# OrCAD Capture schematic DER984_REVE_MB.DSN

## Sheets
1 PAGE1: size B; title: 720W, 48V  LCS_SR; rev: A
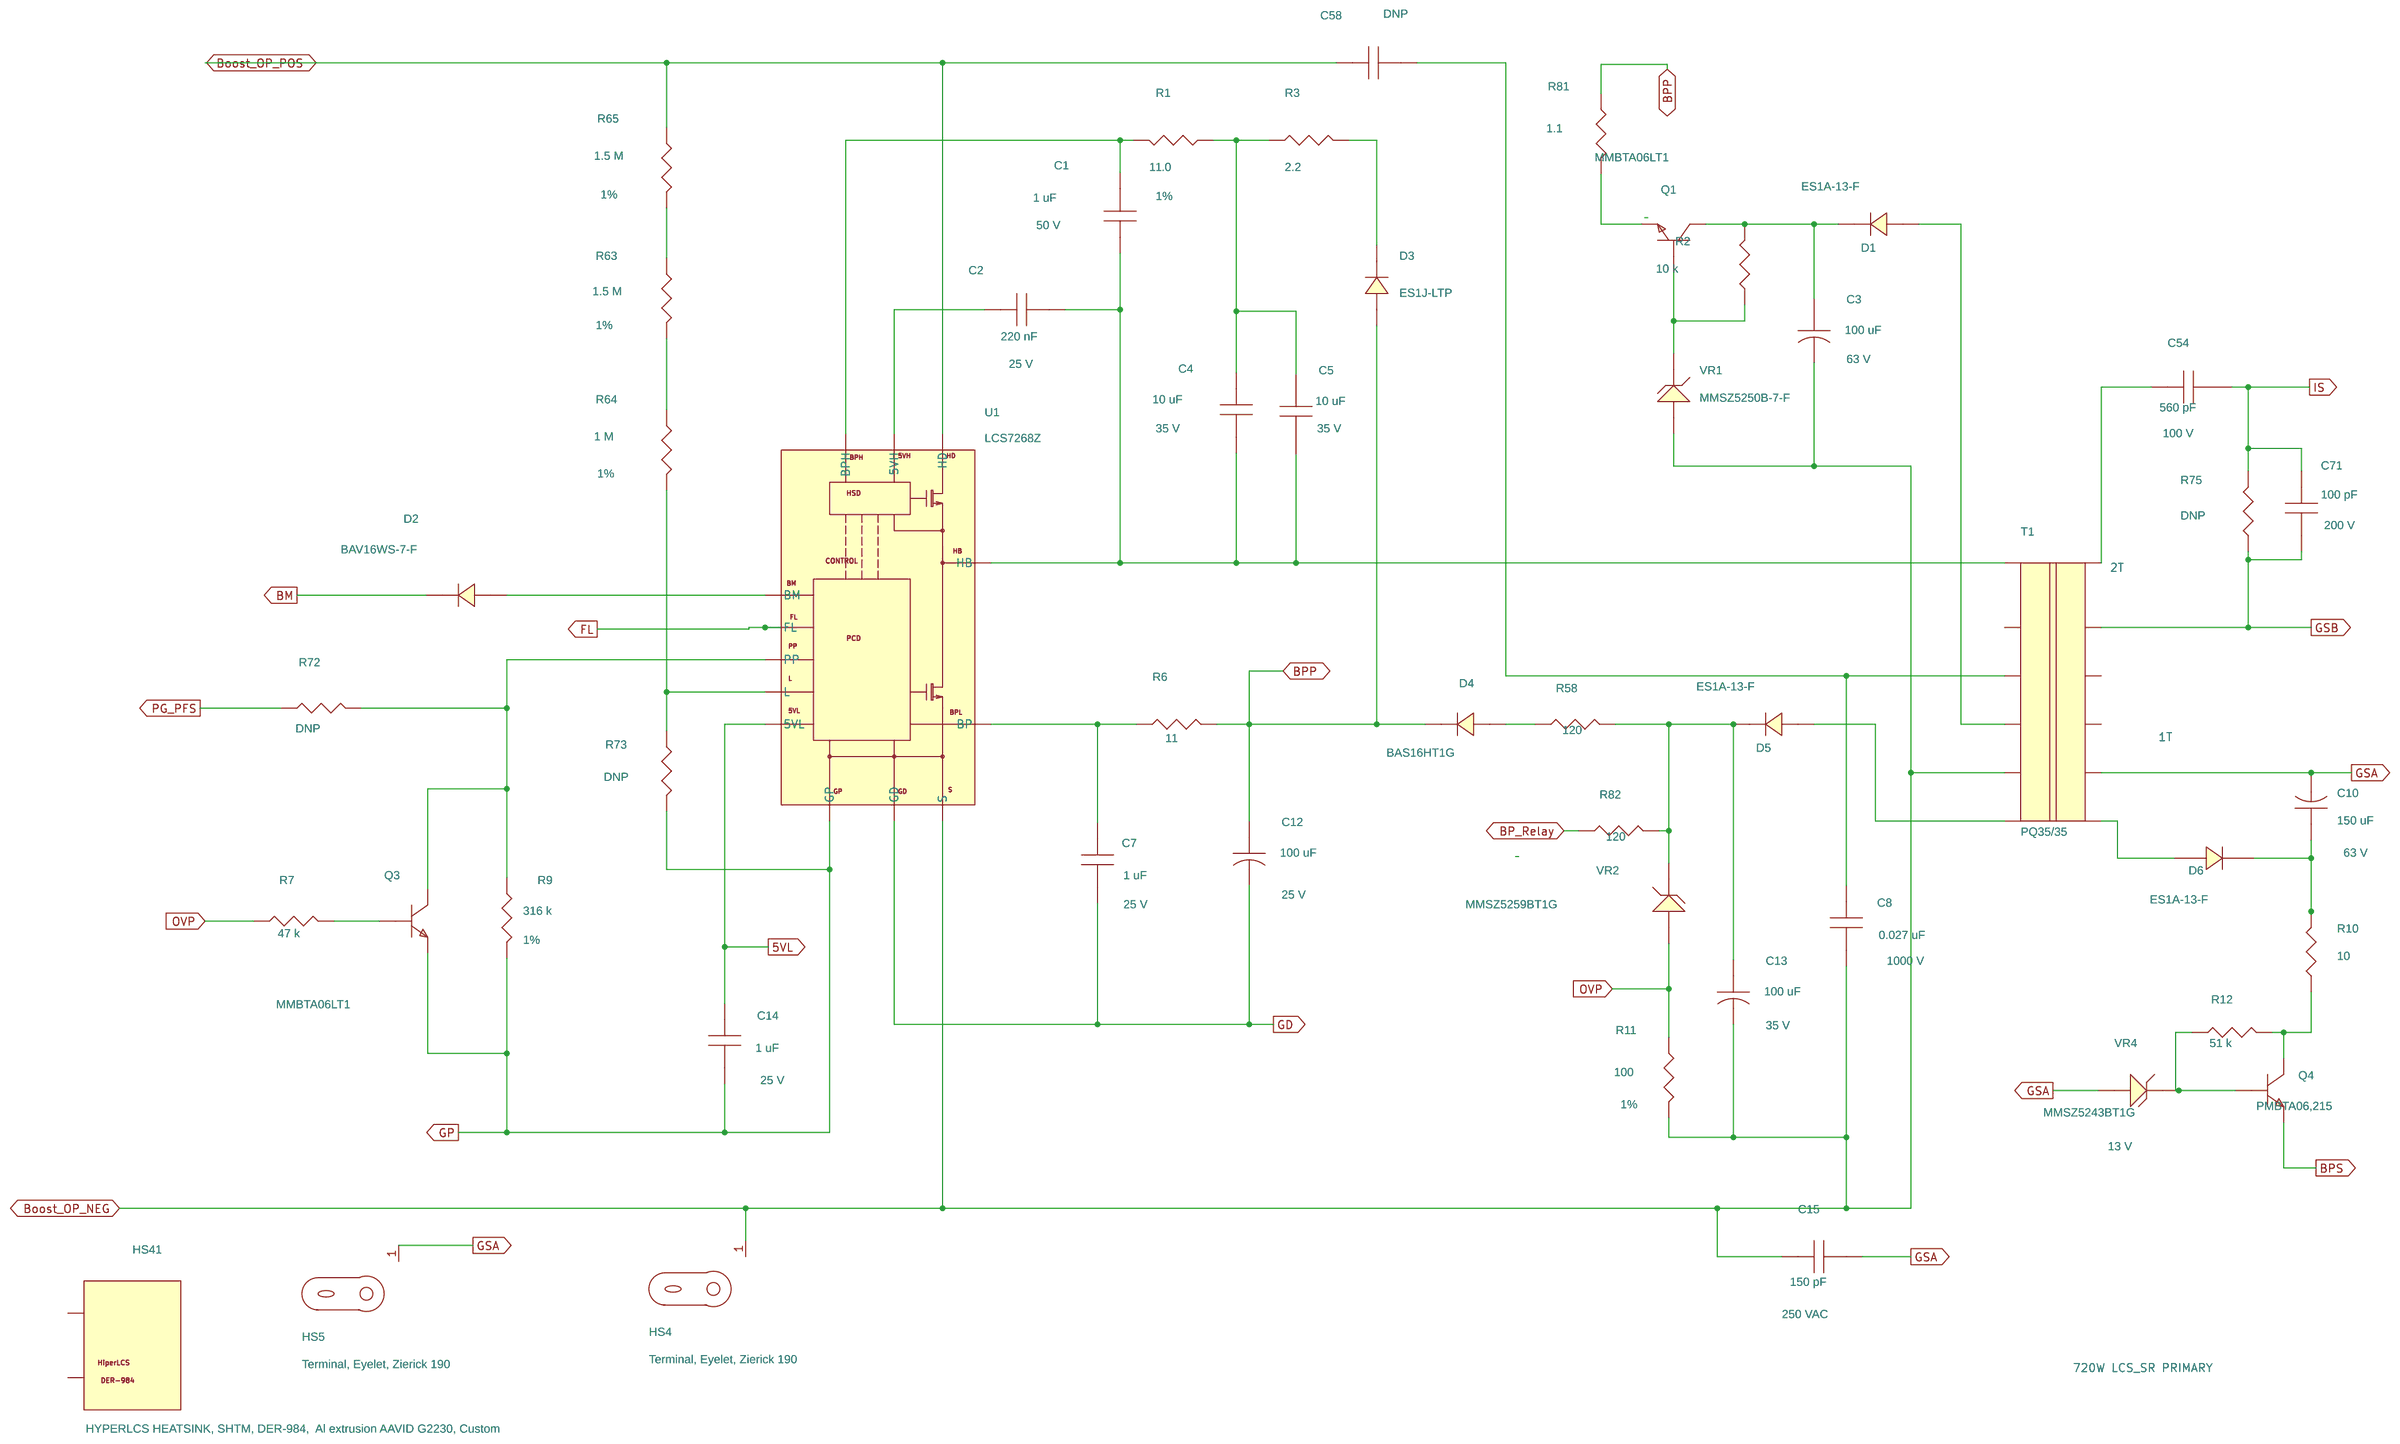
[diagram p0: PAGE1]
2 PAGE2: size B; title: 720W, 48V LCS_SR
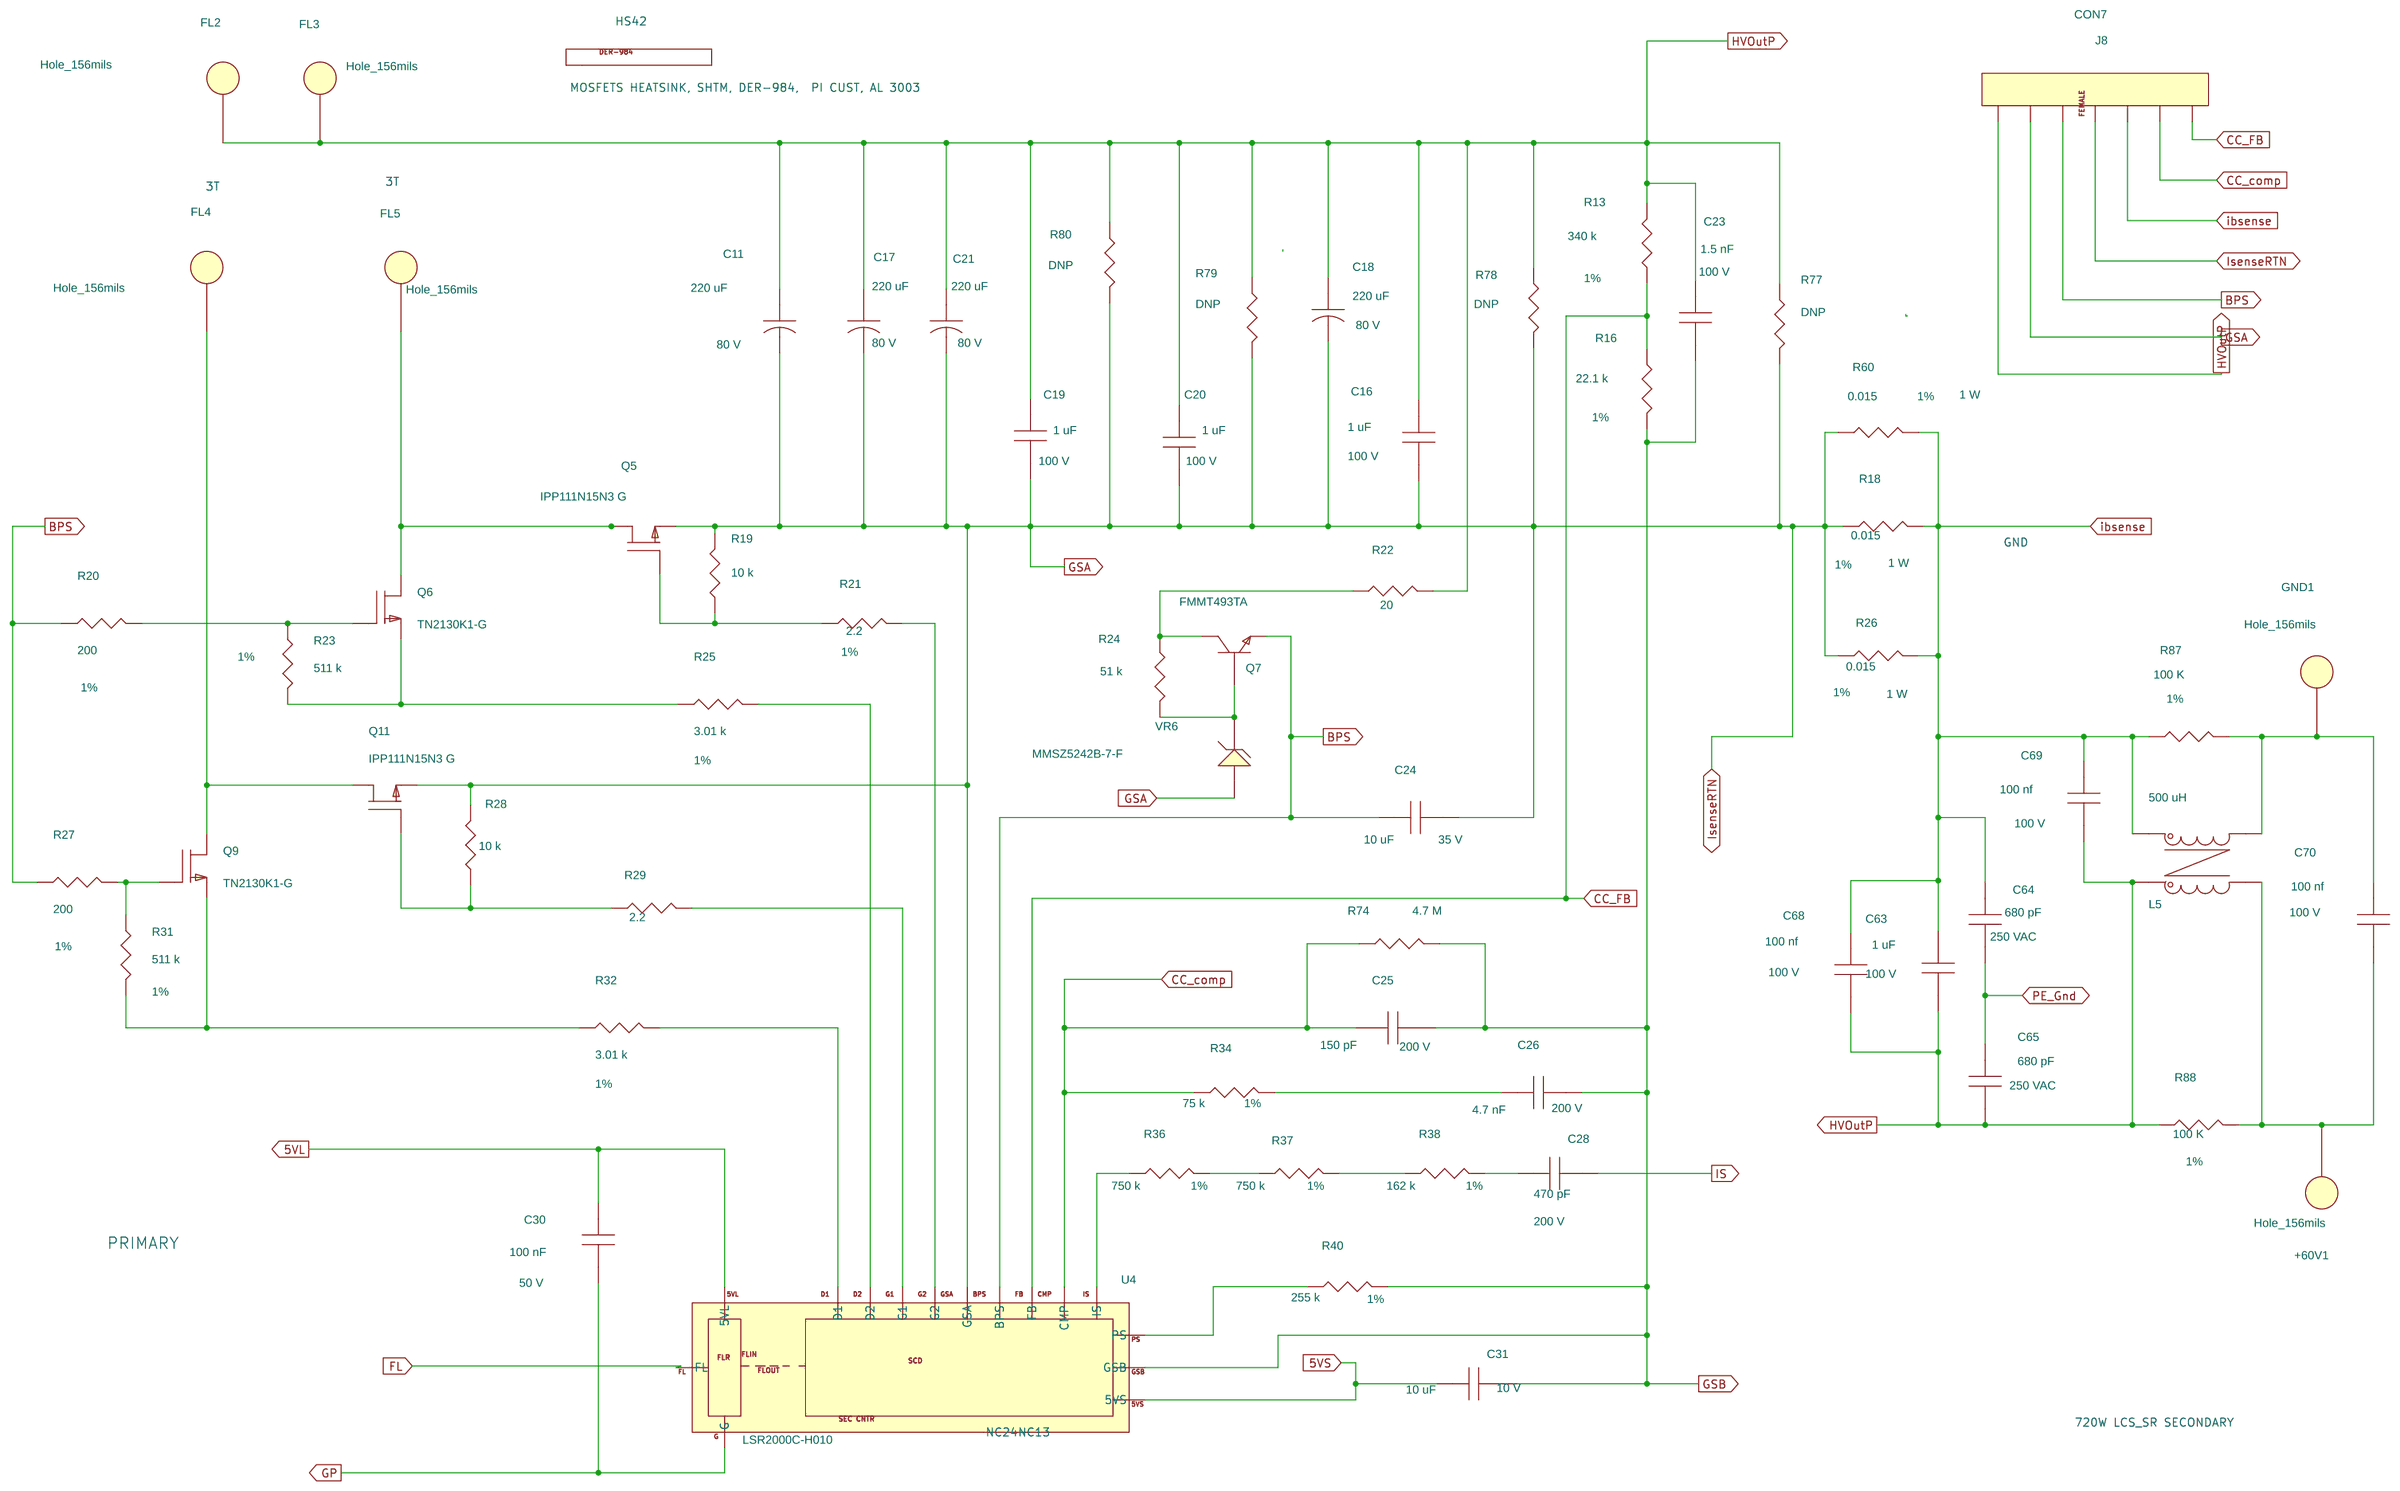
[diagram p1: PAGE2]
3 PAGE3: size C
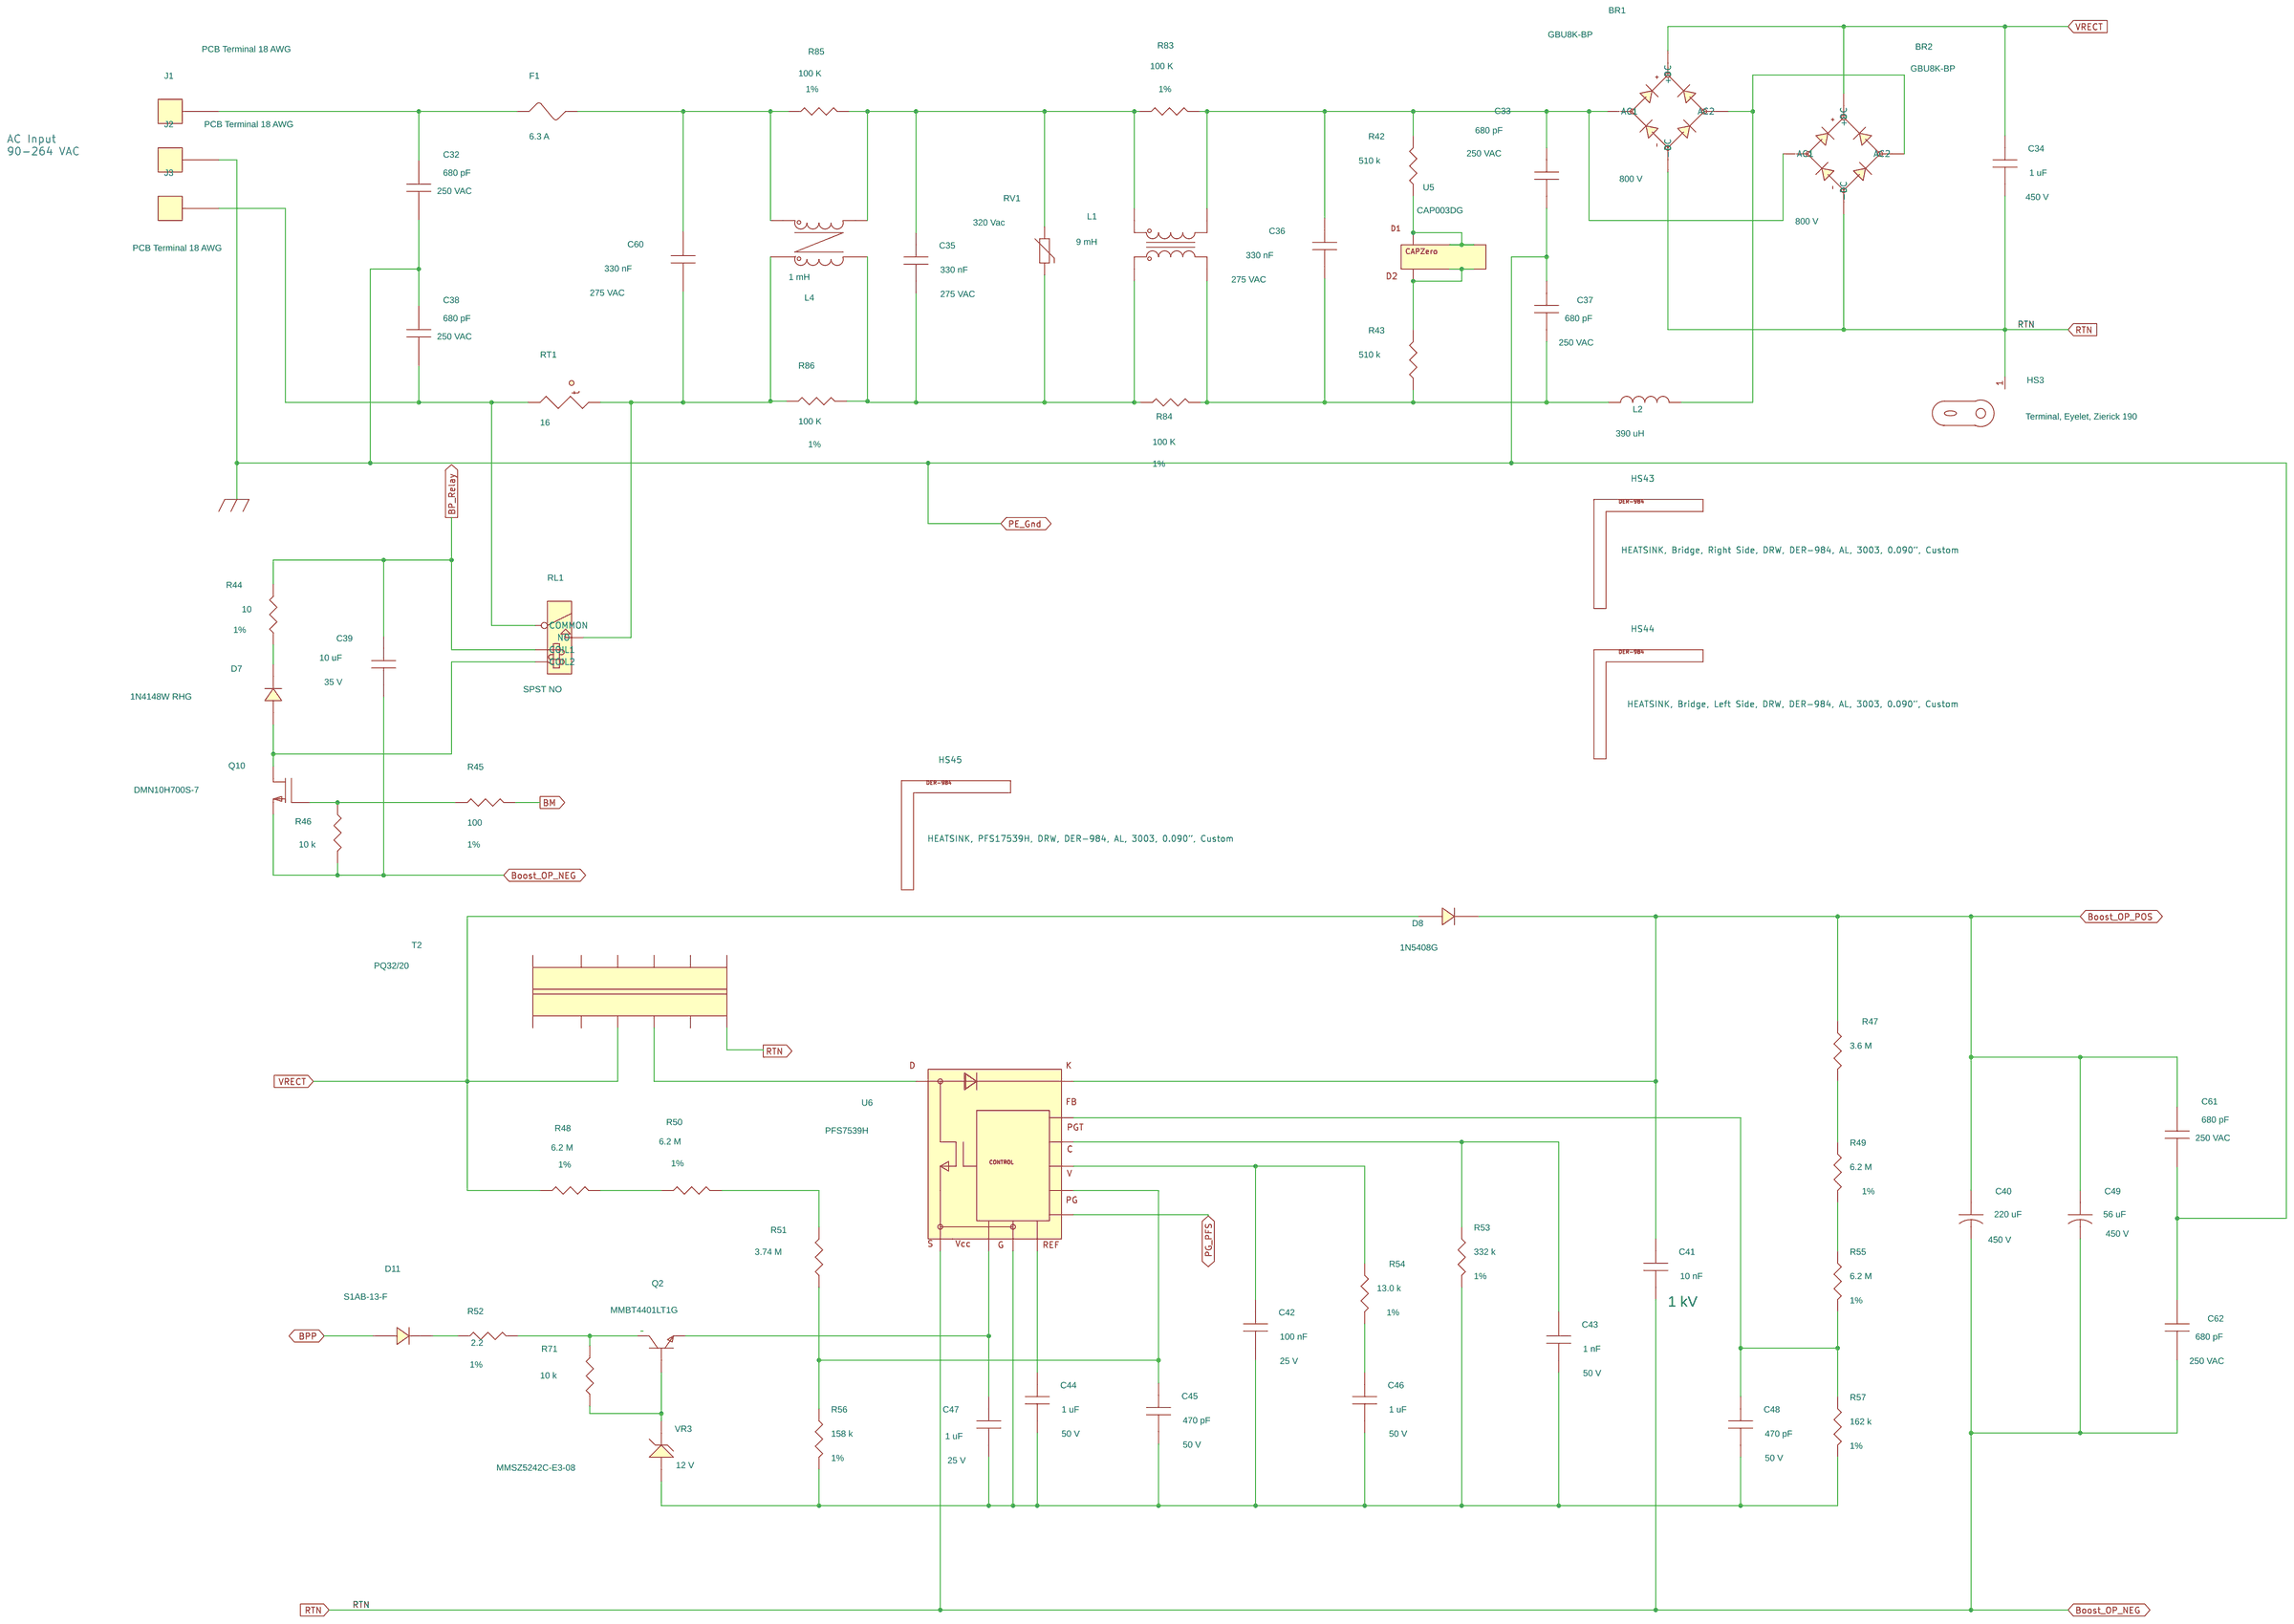
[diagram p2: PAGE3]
4 PAGE4: size C
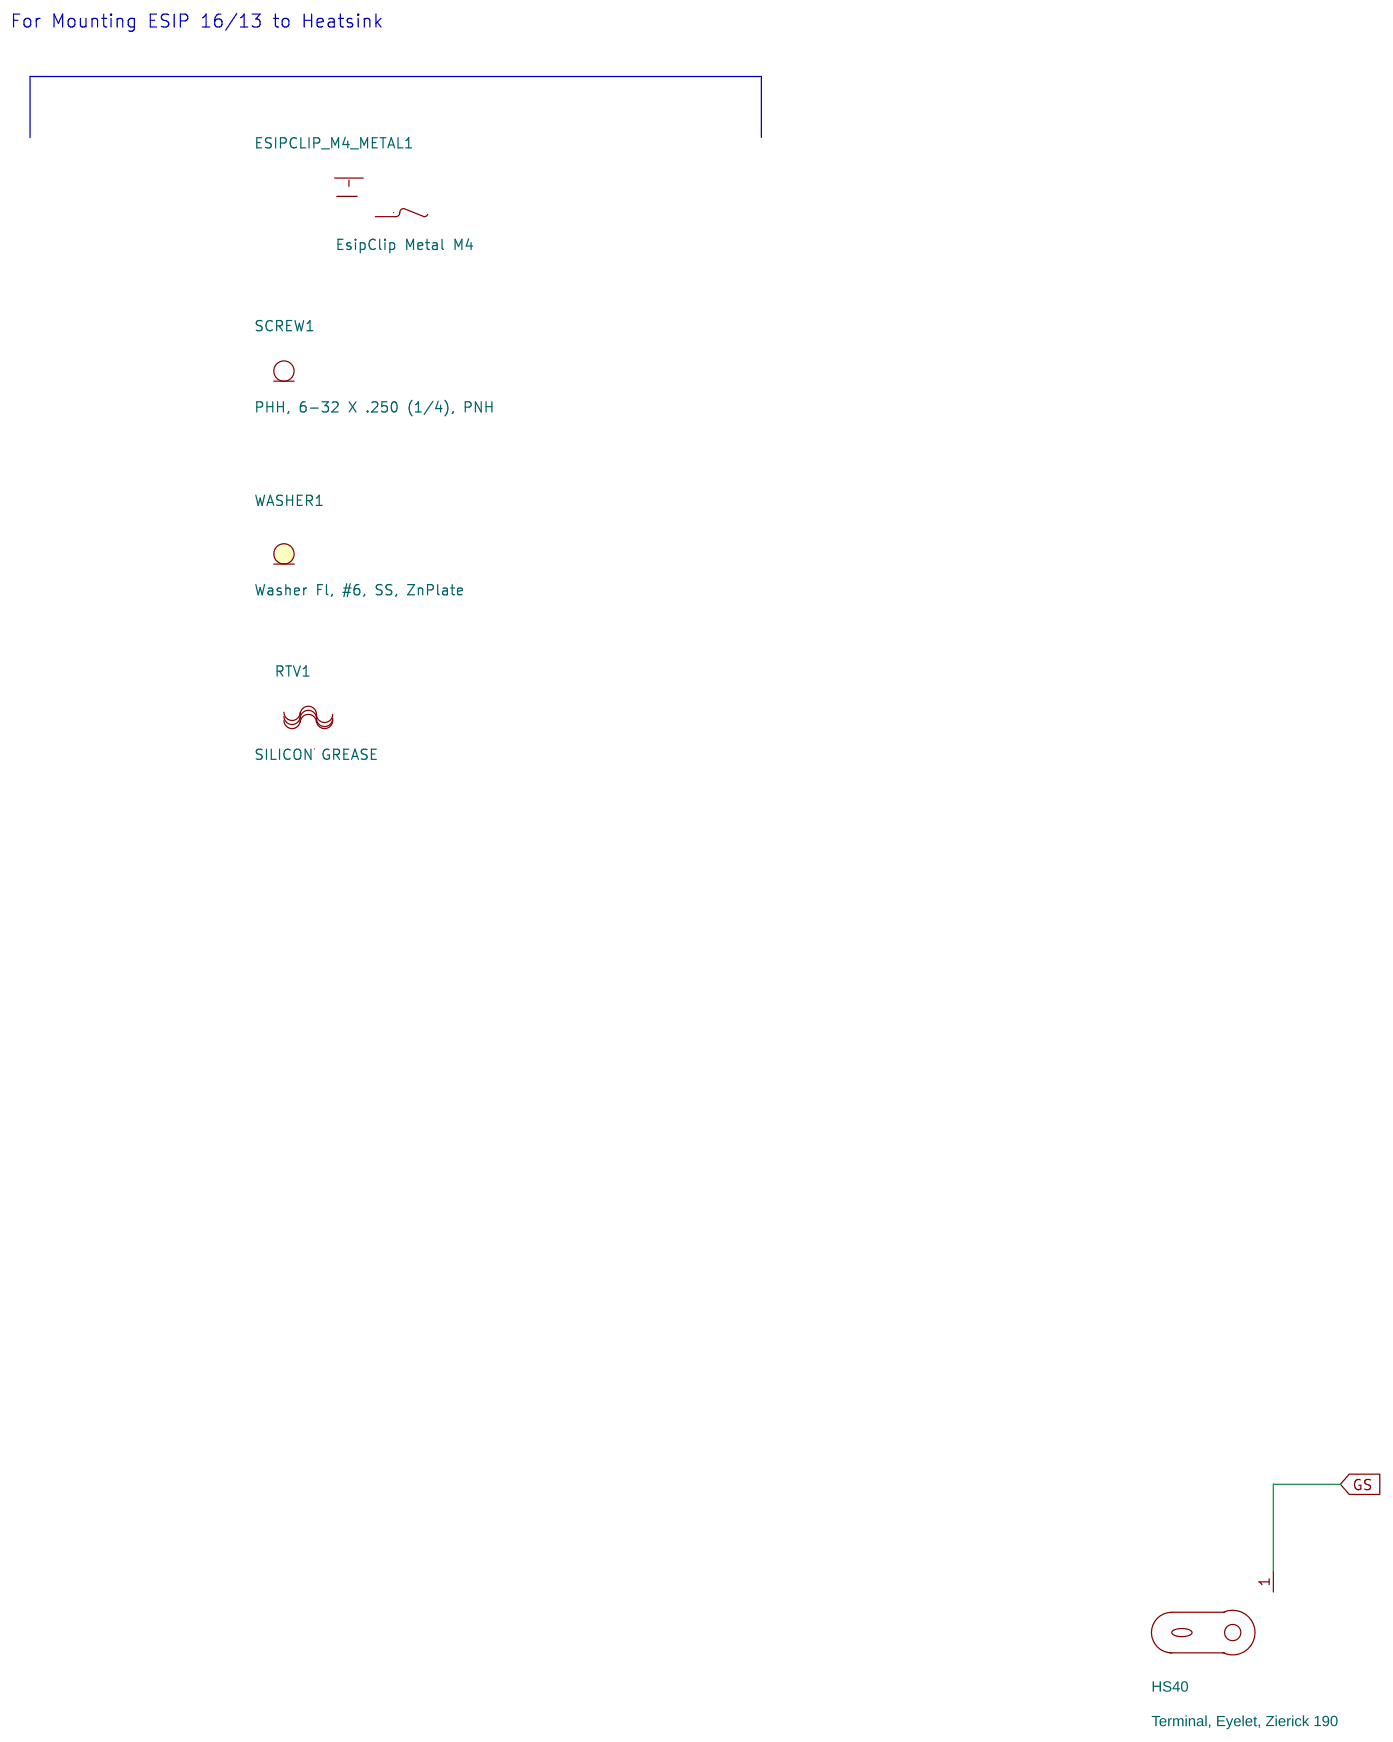
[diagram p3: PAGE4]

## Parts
sheet PAGE1
C1  1 uF  [pismc0805]
C2  220 nF  [pismc0805]
C3  100 uF  [pipolcapclyd320ls140030]
C4  10 uF  [pismc0805]
C5  10 uF  [pismc0805]
C7  1 uF  [pismc0805]
C8  0.027 uF  [pinpxcaprad18x7p5mm040]
C10  150 uF  [pipolcapclyd320ls140030]
C12  100 uF  [pipolcapcyld250ls100030]
C13  100 uF  [pipolcapcyld250ls100030]
C14  1 uF  [pismc0805]
C15  150 pF  [pinpcaprad394x275394030]
C54  560 pF  [pismc0805]
C58  DNP  [pi_np_caprad709x276ls590d050]
C71  100 pF  [pismc0805]
D1  ES1A-13-F  [pismdo214ac12]
D2  BAV16WS-7-F  [pismsod323]
D3  ES1J-LTP  [pismdo214ac12]
D4  BAS16HT1G  [pismdsod323]
D5  ES1A-13-F  [pismdo214ac12]
D6  ES1A-13-F  [pismdo214ac12]
HS4  Terminal, Eyelet, Zierick 190  [pi_zierick190_eyelet]
HS5  Terminal, Eyelet, Zierick 190  [pi_zierick190_eyelet]
HS41  HYPERLCS HEATSINK, SHTM, DER-984,  Al extrusion AAVID G2230, Custom
Q1  MMBTA06LT1  [pismsot23123_1]
Q3  MMBTA06LT1  [pismsot23123_1]
Q4  PMBTA06,215  [pismsot23123_1]
R1  11.0  [pismr0805]
R2  10 k  [pismr0805]
R3  2.2  [pismr0805]
R6  11  [pismr0805]
R7  47 k  [pismr0603]
R9  316 k  [pismr0805]
R10  10  [pismr1206]
R11  100  [pismr0805]
R12  51 k  [pismr0805]
R58  120  [pismr1206]
R63  1.5 M  [pismr0805]
R64  1 M  [pismr0805]
R65  1.5 M  [pismr0805]
R72  DNP  [pismr0805]
R73  DNP  [pismr0805]
R75  DNP  [pismr0805]
R81  1.1  [pismr0805]
R82  120  [pismr0805]
T1  PQ35/35  [pi_bobbin_bpq35_35_12p]
U1  LCS7268Z  [pi_PoweDIP_B18pA]
VR1  MMSZ5250B-7-F  [pi_sm_sod-123_12]
VR2  MMSZ5259BT1G  [pi_sm_sod-123_12]
VR4  MMSZ5243BT1G  [pi_sm_sod-123_12]
sheet PAGE2
+60V1  Hole_156mils  [pi_hole_156mil]
C11  220 uF  [pipolcapcyld400ls200040]
C16  1 uF  [pismc0805]
C17  220 uF  [pipolcapcyld400ls200040]
C18  220 uF  [pipolcapcyld400ls200040]
C19  1 uF  [pismc0805]
C20  1 uF  [pismc0805]
C21  220 uF  [pipolcapcyld400ls200040]
C23  1.5 nF  [pismc1206]
C24  10 uF  [pismc1206]
C25  150 pF  [pismc0805]
C26  4.7 nF  [pismc0805]
C28  470 pF  [pismc0603]
C30  100 nF  [pismc0805]
C31  10 uF  [pismc0805]
C63  1 uF  [pismc0805]
C64  680 pF  [pinpycaprad470x210ls380040]
C65  680 pF  [pinpycaprad470x210ls380040]
C68  100 nf  [pismc0805]
C69  100 nf  [pismc0805]
C70  100 nf  [pismc0805]
FL2  Hole_156mils  [pi_hole_156mil]
FL3  Hole_156mils  [pi_hole_156mil]
FL4  Hole_156mils  [pi_hole_156mil]
FL5  Hole_156mils  [pi_hole_156mil]
GND1  Hole_156mils  [pi_hole_156mil]
HS42  MOSFETS HEATSINK, SHTM, DER-984,  PI CUST, AL 3003  [PI_hs_0P_DER-984MOSFET]
J8  CON7  [PI_HDRF_1X7_Hirose]
L5  500 uH  [pi_CMC_500uH]
Q5  IPP111N15N3 G  [PITO220ABVF1]
Q6  TN2130K1-G  [pismsot23123_1]
Q7  FMMT493TA  [pismsot23123_1]
Q9  TN2130K1-G  [pismsot23123_1]
Q11  IPP111N15N3 G  [PITO220ABVF1]
R13  340 k  [pismr0805]
R16  22.1 k  [pismr0805]
R18  0.015  [pismr1206]
R19  10 k  [pismr0805]
R20  200  [pismr0805]
R21  2.2  [pismr1206]
R22  20  [pismr1206]
R23  511 k  [pismr0805]
R24  51 k  [pismr0805]
R25  3.01 k  [pismr0805]
R26  0.015  [pismr1206]
R27  200  [pismr0805]
R28  10 k  [pismr0805]
R29  2.2  [pismr1206]
R31  511 k  [pismr0805]
R32  3.01 k  [pismr0805]
R34  75 k  [pismr1206]
R36  750 k  [pismr0603]
R37  750 k  [pismr0603]
R38  162 k  [pismr0805]
R40  255 k  [pismr0805]
R60  0.015  [pismr1206]
R74  4.7 M  [pismr0805]
R77  DNP  [pismr1206]
R78  DNP  [pismr1206]
R79  DNP  [pismr1206]
R80  DNP  [pismr1206]
R87  100 K  [pismr0603]
R88  100 K  [pismr0603]
U4  LSR2000C-H010  [pi_ic_insop_24D]
VR6  MMSZ5242B-7-F  [pi_sm_sod-123_12]
sheet PAGE3
BR1  GBU8K-BP  [pidaxbridgegbu8]
BR2  GBU8K-BP  [pidaxbridgegbu8]
C32  680 pF  [pinpycaprad470x210ls380040]
C33  680 pF  [pinpycaprad470x210ls380040]
C34  1 uF  [pinpcaprad_12p6x9p2_ls10_d40]
C35  330 nF  [pinp_xcaprad15x8p5x14Hd040]
C36  330 nF  [pinp_xcaprad15x8p5x14Hd040]
C37  680 pF  [pinpycaprad470x210ls380040]
C38  680 pF  [pinpycaprad470x210ls380040]
C39  10 uF  [pismc0805]
C40  220 uF  [pi_polcap_d1000ls394d080]
C41  10 nF  [pi_np_cap250x200ls170d030]
C42  100 nF  [pismc0805]
C43  1 nF  [pismc0805]
C44  1 uF  [pismc0805]
C45  470 pF  [pismc0805]
C46  1 uF  [pismc0805]
C47  1 uF  [pismc0805]
C48  470 pF  [pismc0805]
C49  56 uF  [pipolcapclyd500ls200040]
C60  330 nF  [pinp_xcaprad15x8p5x14Hd040]
C61  680 pF  [pinpycaprad470x210ls380040]
C62  680 pF  [pinpycaprad470x210ls380040]
D7  1N4148W RHG  [pi_sm_sod-123_12]
D8  1N5408G  [pidv300x200x060do15d0201ad]
D11  S1AB-13-F  [pismsmb]
F1  6.3 A  [PI_V_AX_BEL_0697H]
HS3  Terminal, Eyelet, Zierick 190  [pi_zierick190_eyelet]
HS43  HEATSINK, Bridge, Right Side, DRW, DER-984, AL, 3003, 0.090”, Custom  [PI_hs_0P_DER-984RBridge]
HS44  HEATSINK, Bridge, Left Side, DRW, DER-984, AL, 3003, 0.090”, Custom  [PI_hs_0P_DER-984LBridge]
HS45  HEATSINK, PFS17539H, DRW, DER-984, AL, 3003, 0.090”, Custom  [PI_hs_0P_DER-984PFS]
J1  PCB Terminal 18 AWG  [pi_hole_18awg]
J2  PCB Terminal 18 AWG  [pi_hole_18awg]
J3  PCB Terminal 18 AWG  [pi_hole_18awg]
L1  9 mH  [pi_ind_4p_500x1050ls450d46]
L2  390 uH  [pitoroid2p650x1170ls560060]
L4  1 mH  [pi_CMC_1mH]
Q2  MMBT4401LT1G  [pismsot23123_1]
Q10  DMN10H700S-7  [pismsot23123_1]
R42  510 k  [pismr1206]
R43  510 k  [pismr1206]
R44  10  [pismr0603]
R45  100  [pismr0603]
R46  10 k  [pismr0402]
R47  3.6 M  [pismr0805]
R48  6.2 M  [pismr1206]
R49  6.2 M  [pismr1206]
R50  6.2 M  [pismr1206]
R51  3.74 M  [pismr1206]
R52  2.2  [pismr0603]
R53  332 k  [pismr0805]
R54  13.0 k  [pismr0805]
R55  6.2 M  [pismr1206]
R56  158 k  [pismr0805]
R57  162 k  [pismr0805]
R71  10 k  [pismr0805]
R83  100 K  [pismr0603]
R84  100 K  [pismr0603]
R85  100 K  [pismr0603]
R86  100 K  [pismr0603]
RL1  SPST NO  [pi_rly-omron-g6rl-1a]
RT1  16  [pirad800x250ls330052]
RV1  320 Vac  [pidisc610x212ls295x95040]
T2  PQ32/20  [pi_bobbin_bpq32_20_12p]
U5  CAP003DG  [pi_ic_smd_so8_capzero]
U6  PFS7539H  [pi_ic_eesip_socket]
VR3  MMSZ5242C-E3-08  [pi_sm_sod-123_12]
sheet PAGE4
ESIPCLIP_M4_METAL1  EsipClip Metal M4
HS40  Terminal, Eyelet, Zierick 190  [pi_zierick190_eyelet]
RTV1  SILICON GREASE
SCREW1  PHH, 6-32 X .250 (1/4), PNH
WASHER1  Washer Fl, #6, SS, ZnPlate

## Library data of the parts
C1 = CAP_NP: Disp_Voltage: 50 V; Part Number: 20-00853-00; ROOM: 1; Voltage: 50 V
C2 = CAP_NP: Disp_Voltage: 25 V; Part Number: 20-00237-00; ROOM: 1; Voltage: 25 V
C3 = CAP_POL: Disp_Voltage: 63 V; FPLIST: pipolcapclyd320ls140030,pipolcapclyd320ls140030430h; Part Number: 20-00154-00; ROOM: 1; Voltage: 63 V
C4 C5 = CAP_NP: ALT_SYMBOLS: pismc0805_1; Disp_Voltage: 35 V; FPLIST: pismc0805,pismc0805_1; Part Number: 20-01692-00; ROOM: 1; Voltage: 35 V
C7 C14 = CAP_NP: Disp_Voltage: 25 V; Part Number: 20-09171-00; ROOM: 1; Voltage: 25 V
C8 = CAP_NP: ALT_SYMBOLS: pinpxcaprad18x7p5x13p6mm040H; Disp_Voltage: 1000 V; FPLIST: pinpxcaprad18x7p5mm040,pinpxcaprad18x7p5x13p6mm040H; Part Number: 20-01702-00; ROOM: 1; Voltage: 1000 V
C10 = CAP_POL: Disp_Voltage: 63 V; FPLIST: pipolcapclyd320ls140030,pipolcapclyd320ls140030430h; Part Number: 20-00155-00; Voltage: 63 V
C12 = CAP_POL: ALT_SYMBOLS: pipolcapcyld250ls100030h; Disp_Voltage: 25 V; FPLIST: pipolcapcyld250ls100030,pipolcapcyld250ls100030h; Part Number: 20-00027-00; Voltage: 25 V
C13 = CAP_POL: Disp_Voltage: 35 V; Part Number: 20-01206-00; Voltage: 35 V
C15 = CAP_NP: Disp_Voltage: 250 VAC; PCB Editor PCBFP: pinpycaprad540x290ls400040; Part Number: 20-00741-00; ROOM: 1; Tol: 20; Voltage: 250 VAC
C54 = CAP_NP: ALT_SYMBOLS: Unisem_RMCF0805UL; Disp_Voltage: 100 V; FPLIST: pismc0805,Unisem_RMCF0805UL; Part Number: 20-09240-00; Voltage: 100 V
C58 = CAP_NP: ALT_SYMBOLS: pi_np_caprad709x276ls590d050_h; Disp_Voltage: 1600 V; FPLIST: pi_np_caprad709x276ls590d050,pi_np_caprad709x276ls590d050_h; Part Number: 20-00934-00; ROOM: 1; Voltage: 1600 V
C71 = CAP_NP: ALT_SYMBOLS: Unisem_RMCF0805UL; Disp_Voltage: 200 V; FPLIST: pismc0805,Unisem_RMCF0805UL; Part Number: 20-01525-00; Voltage: 200 V
D1 D5 D6 = DIODE: Part Number: 15-00351-00; ROOM: 1
D2 = DIODE: Part Number: 15-00850-00; ROOM: 1
D3 = DIODE: Part Number: 15-01071-00; ROOM: 1
D4 = DIODE: Part Number: 15-00711-00; ROOM: 1
HS3-HS5 HS40 = TERM_EYLT: Part Number: 60-00016-00
HS41 = hs_2P_DER984_HYPERLCS: Part Number: 61-00326-00
Q1 Q3 = NPN_BEC: Part Number: 55-00030-00; ROOM: 1
Q4 = NPN_BEC: Part Number: 55-00178-00; ROOM: 1
R1 = R: Disp_Tol: 1%; Part Number: 05-00496-00; ROOM: 1
R2 = R: Part Number: 05-01543-00; ROOM: 1
R3 = R: Part Number: 05-01455-00; ROOM: 1
R6 = R: Part Number: 05-01472-00; ROOM: 1
R7 = R: Part Number: 05-01728-00; ROOM: 1
R9 = R: Disp_Tol: 1%; Part Number: 05-00828-00; ROOM: 1
R10 = R: Part Number: 05-01304-00; ROOM: 1
R11 = R: Disp_Tol: 1%; Part Number: 05-06641-00; ROOM: 1
R12 R24 = R: ALT_SYMBOLS: Unisem_RMCF0805UL; FPLIST: pismr0805,Unisem_RMCF0805UL; Part Number: 05-01560-00
R58 = R: Part Number: 05-01330-00
R63 R65 = R: Disp_Tol: 1%; Part Number: 05-00880-00
R64 = R: Disp_Tol: 1%; Part Number: 05-00876-00
R72 = R: Disp_Tol: 1%; Part Number: 05-00709-00
R73 = R: ALT_SYMBOLS: pismr0805_1; FPLIST: pismr0805,pismr0805_1; Part Number: 05-03159-00
R75 = R: ALT_SYMBOLS: Unisem_RMCF0805UL; Disp_Tol: 1%; FPLIST: pismr0805,Unisem_RMCF0805UL; Part Number: 05-00691-00; ROOM: 1
R81 = R: Part Number: 05-01448-00; ROOM: 1
R82 = R: Part Number: 05-01497-00
T1 = BPQ35_35_12P_GENERIC: Part Number: 25-00919-00
U1 = HiperLCS2-HB: ALT_SYMBOLS: pi_PoweDIP_B18pNH; FPLIST: pi_PoweDIP_B18pA,pi_PoweDIP_B18pNH; Part Number: 10-01545-00
VR1 = DIODE_ZENER: Part Number: 15-01093-00; ROOM: 1
VR2 = DIODE_ZENER: Part Number: 15-01100-00; ROOM: 1
VR4 = DIODE_ZENER: Disp_Voltage: 13 V; Part Number: 15-00710-00; ROOM: 1
+60V1 FL2-FL5 GND1 = FlyingLead: Part Number: 35-00420-00; ROOM: 2
C11 C17 C18 C21 = CAP_POL: ALT_SYMBOLS: pipolcapcyld400ls200040800h; Disp_Voltage: 80 V; FPLIST: pipolcapcyld400ls200040,pipolcapcyld400ls200040800h; Part Number: 20-09219-00; Voltage: 80 V
C16 C19 C20 C63 = CAP_NP: Disp_Voltage: 100 V; Part Number: 20-01324-00; ROOM: 2; Voltage: 100 V
C23 = CAP_NP: Disp_Voltage: 100 V; Part Number: 20-08687-00; ROOM: 2; Voltage: 100 V
C24 = CAP_NP: ALT_SYMBOLS: CC1206; Disp_Voltage: 35 V; FPLIST: pismc1206,CC1206; Part Number: 20-01479-00; ROOM: 2; Voltage: 35 V
C25 = CAP_NP: ALT_SYMBOLS: Unisem_RMCF0805UL; Disp_Voltage: 200 V; FPLIST: pismc0805,Unisem_RMCF0805UL; Part Number: 20-09098-00; Voltage: 200 V
C26 = CAP_NP: ALT_SYMBOLS: Unisem_RMCF0805UL; Disp_Voltage: 200 V; FPLIST: pismc0805,Unisem_RMCF0805UL; Part Number: 20-08570-00; Voltage: 200 V
C28 = CAP_NP: Disp_Voltage: 200 V; Part Number: 20-00529-00; ROOM: 2; Voltage: 200 V
C30 = CAP_NP: Disp_Voltage: 50 V; Part Number: 20-00904-00; ROOM: 2; Voltage: 50 V
C31 = CAP_NP: Disp_Voltage: 10 V; Part Number: 20-01694-00; ROOM: 2; Voltage: 10 V
C32 C33 C37 C38 C61 C62 C64 C65 = CAP_NP: Disp_Voltage: 250 VAC; Part Number: 20-00374-00; Tol: 20; Voltage: 250 VAC
C68-C70 = CAP_NP: Disp_Voltage: 100 V; Part Number: 24-00026-00; ROOM: 2; Voltage: 100 V
HS42 = hs_0P_DER984: Part Number: 61-00325-00
J8 = HEADER_7: Part Number: 35-00431-00
L5 = TORRID_4P_14_23: Part Number: 32-00449-00
Q5 Q11 = FET_N_GDS: ALT_SYMBOLS: PI_TO220AB,PITO220ABVF1R,pidvto2203vf1h; FPLIST: PITO220ABVF1,PI_TO220AB,pidvto2203vf1h; Part Number: 50-00149-00; ROOM: 2
Q6 Q9 = FET_N_GSD: Part Number: 50-00314-00
Q7 = NPN_BEC: Part Number: 55-00104-00; ROOM: 2
R13 = R: Disp_Tol: 1%; Part Number: 05-00831-00; ROOM: 2
R16 = R: Disp_Tol: 1%; Part Number: 05-00717-00; ROOM: 2
R18 R26 R60 = R: Disp_Power: 1 W; Disp_Tol: 1%; Part Number: 05-06450-00
R19 R28 = R: Part Number: 05-01543-00; ROOM: 2
R20 R27 = R: Disp_Tol: 1%; Part Number: 05-00617-00; ROOM: 2
R21 = R: Disp_Tol: 1%; Part Number: 05-00489-00; ROOM: 2
R22 = R: Part Number: 05-01311-00
R23 R31 = R: Disp_Tol: 1%; Part Number: 05-00848-00; ROOM: 2
R25 R32 = R: ALT_SYMBOLS: Unisem_RMCF0805UL; Disp_Tol: 1%; FPLIST: pismr0805,Unisem_RMCF0805UL; Part Number: 05-03354-00
R29 = R: Part Number: 05-01288-00; ROOM: 2
R34 = R: Disp_Power: 0.25 W; Disp_Tol: 1%; Part Number: 05-06690-00
R36 R37 = R: Disp_Tol: 1%; Part Number: 05-01258-00; ROOM: 2
R38 = R: ALT_SYMBOLS: Unisem_RMCF0805UL; Disp_Tol: 1%; FPLIST: pismr0805,Unisem_RMCF0805UL; Part Number: 05-00800-00; ROOM: 2
R40 = R: ALT_SYMBOLS: Unisem_RMCF0805UL; Disp_Tol: 1%; FPLIST: pismr0805,Unisem_RMCF0805UL; Part Number: 05-00819-00
R74 = R: ALT_SYMBOLS: Unisem_RMCF0805UL; FPLIST: pismr0805,Unisem_RMCF0805UL; Part Number: 05-01606-00
R77-R80 = R: Disp_Tol: 1%; Part Number: 05-00327-00
R83-R88 = R: Disp_Tol: 1%; Part Number: 05-06561-00
U4 = HiperLCS2-SR: Part Number: 10-01122-10
VR6 = DIODE_ZENER: Part Number: 15-01090-00; ROOM: 2
BR1 BR2 = DISCRETE_BRIDGE_+~~-: Disp_Voltage: 800 V; Part Number: 15-00347-00
C34 = CAP_NP: ALT_SYMBOLS: pinpcaprad_12p6x9p2_ls10_d400H; Disp_Voltage: 450 V; FPLIST: pinpcaprad_12p6x9p2_ls10_d40,pinpcaprad_12p6x9p2_ls10_d40H; Part Number: 20-09184-00; Voltage: 450 V
C35 C36 C60 = CAP_NP: ALT_SYMBOLS: pinp_xcaprad15x8p5x14Hd040H; Disp_Voltage: 275 VAC; FPLIST: pinp_xcaprad15x8p5x14Hd040,pinp_xcaprad15x8p5x14Hd040H; Part Number: 20-09095-00; Voltage: 275 VAC
C39 = CAP_NP: ALT_SYMBOLS: pismc0805_1; Disp_Voltage: 35 V; FPLIST: pismc0805,pismc0805_1; Part Number: 20-01692-00; Voltage: 35 V
C40 = CAP_POL: Disp_Voltage: 450 V; Part Number: 20-08730-00; Voltage: 450 V
C41 = CAP_NP: Disp_Voltage: 1 kV; Part Number: 20-00894-00; Voltage: 1 kV
C42 = CAP_NP: Disp_Voltage: 25 V; Part Number: 20-08599-00; Voltage: 25 V
C43 = CAP_NP: Disp_Voltage: 50 V; Part Number: 20-08750-00; Voltage: 50 V
C44 = CAP_NP: Disp_Voltage: 50 V; Part Number: 20-01513-00; Voltage: 50 V
C45 C48 = CAP_NP: Disp_Voltage: 50 V; Part Number: 20-00205-00; Voltage: 50 V
C46 = CAP_NP: Disp_Voltage: 50 V; Part Number: 20-00853-00; Voltage: 50 V
C47 = CAP_NP: Disp_Voltage: 25 V; Part Number: 20-00923-00; Voltage: 25 V
C49 = CAP_POL: ALT_SYMBOLS: pipolcapclyd500ls2000401200lh; Disp_Voltage: 450 V; FPLIST: pipolcapclyd500ls200040,pipolcapclyd500ls2000401200lh; Part Number: 20-09230-00; Voltage: 450 V
D7 = DIODE: ALT_SYMBOLS: pi_sm_sod-123_12_1; FPLIST: pi_sm_sod-123_12,pi_sm_sod-123_12_1; Part Number: 15-01269-00
D8 = DIODE: ALT_SYMBOLS: pidv300x472x060do14wbead,pidax800x225060do15do201ad,pidv300x200x060do14wbead; FPLIST: pidv300x200x060do15d0201ad,pidv300x472x060do14wbead,pidax800x225060do15do201ad,pidv300x200x060do14wbead; Part Number: 15-01651-00
D11 = DIODE: Part Number: 15-00994-00
F1 = FUSE: ALT_SYMBOLS: PI_V_AX_BEL_0697H_H; FPLIST: PI_V_AX_BEL_0697H,PI_V_AX_BEL_0697H_H; Part Number: 40-00089-00
HS43 = hs_0P_DER984L: Part Number: 61-00334-00
HS44 = hs_0P_DER984L: Part Number: 61-00335-00
HS45 = hs_0P_DER984L: Part Number: 61-00336-00
J1-J3 = TERM_1Pin: Part Number: 35-00007-00
L1 = INDUCTOR_4P_revB: Part Number: 30-00235-00
L2 = INDUCTOR: Part Number: 32-00190-00
L4 = TORRID_4P_14_23: Part Number: 32-00448-00
Q2 = NPN_BEC: Part Number: 55-00152-00
Q10 = FET_N_GSD: Part Number: 50-00416-00
R42 R43 = R: Part Number: 05-01417-00
R44 = R: Disp_Tol: 1%; Part Number: 05-03548-00
R45 = R: ALT_SYMBOLS: Unisem_RMCF0603UL; Disp_Tol: 1%; FPLIST: pismr0603,Unisem_RMCF0603UL; Part Number: 05-00982-00
R46 = R: Part Number: 05-06235-00
R47 = R: Part Number: 05-01603-00
R48-R50 R55 = R: Disp_Tol: 1%; Part Number: 05-05567-00
R51 = R: Part Number: 05-05572-00
R52 = R: Disp_Tol: 1%; Part Number: 05-01278-00
R53 = R: Disp_Tol: 1%; Part Number: 05-00830-00
R54 = R: Disp_Tol: 1%; Part Number: 05-06367-00
R56 = R: Disp_Tol: 1%; Part Number: 05-00799-00
R57 = R: ALT_SYMBOLS: Unisem_RMCF0805UL; Disp_Tol: 1%; FPLIST: pismr0805,Unisem_RMCF0805UL; Part Number: 05-00800-00
R71 = R: Part Number: 05-01543-00
RL1 = RELAY_SPST_NO_OMRON-G6RL: Part Number: 66-00123-00
RT1 = THERMISTOR: Part Number: 90-00003-00
RV1 = VARISTOR: Part Number: 85-00034-00
T2 = BPQ32_20_12P_GENERIC: Part Number: 25-00077-00
U5 = CAPZero: Part Number: 10-00391-00
U6 = DEV_HIPERPFS-3-eSIP-16C: ALT_SYMBOLS: pi_ic_esip16-13_socket_hpii ,pi_ic_esip16-13_oval_hpii,pi_ic_eesip_socket; FPLIST: pi_ic_esip16-13_slot_hpii,pi_ic_esip16-13_socket_hpii,pi_ic_esip16-13_oval_hpii,pi_ic_eesip_socket; Part Number: 10-00704-00
VR3 = DIODE_ZENER: Disp_Voltage: 12 V; Part Number: 15-01691-00
ESIPCLIP_M4_METAL1 = EsipClip_Metal_M4: Part Number: 60-00042-00
RTV1 = RTV: Part Number: 66-00084-00
SCREW1 = SCR_6-32: Part Number: 75-00007-00
WASHER1 = WASH_FLAT_6: Part Number: 75-00167-00

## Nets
5VL: C14.1 C30.1 U1.7(5VL) U4.15(5VL)
5VS: C31.1 U4.1(5VS)
GND_EARTH: C32.2 C33.2 C37.1 C38.1 C61.2 C62.1 C64.2 C65.1 J2.1
BM: D2.1 R45.2
Boost_OP_NEG: BR1.4(-DC) BR2.4(-DC) C3.2 C8.2 C13.2 C15.1 C34.2 C39.2 C40.2 C41.2 C49.2 C62.2 HS3.1 HS4.1 Q10.2(S) R11.2 R46.2 T1.5 T2.6 U1.11(S) U6.10(S1) VR1.2
Boost_OP_POS: C40.1 C41.1 C49.1 C58.1 C61.1 D8.1 R47.1 R65.1 U1.20(HD) U6.16(K)
BP_Relay: C39.1 R44.1 R82.1 RL1.1(COIL1)
BPP: C12.1 D3.2 D4.1 D11.2 R6.2 R81.1
BPS: C24.1 J8.3 Q4.2(EMITTER) Q7.2(EMITTER) R20.1 R27.1 U4.7(BPS)
CC_comp: C25.1 J8.6 R34.1 R74.1 U4.4(CMP)
CC_FB: J8.7 R13.2 R16.1 U4.5(FB)
FL: U1.6(FL) U4.14(FL)
GD: C7.2 C12.2 U1.10(GD)
GP: C14.2 C30.2 Q3.2(EMITTER) R9.2 R73.2 U1.4(GP) U4.16(G)
GS: HS40.1
GSA: C10.2 C11.2 C15.2 C16.2 C17.2 C18.2 C19.2 C20.2 C21.2 C24.2 HS5.1 J8.2 J8.4 Q5.3(S) Q11.3(S) R18.1 R19.1 R26.1 R28.1 R60.1 R77.2 R78.2 R79.2 R80.2 T1.8 U4.12(GSA) VR4.2 VR6.2
GSB: C23.2 C25.2 C26.2 C31.2 C71.2 R16.2 R40.2 R74.2 R75.2 T1.11 U4.2(GSB)
HVOutP: C11.1 C16.1 C17.1 C18.1 C19.1 C20.1 C21.1 C23.1 C63.2 C65.2 C68.2 C69.2 FL2.1 FL3.1 J8.1 L5.2 R13.1 R22.2 R77.1 R78.1 R79.1 R80.1 R88.1
ibsense: C63.1 C64.1 C68.1 C69.1 J8.5 L5.1 R18.2 R26.2 R60.2 R87.1
IS: C28.2 C54.2 C71.1 R75.1
NC: U6.14(NC)
OVP: R7.1 R11.1 VR2.2
PG_PFS: R72.1 U6.8(PG)
SOURCE: U6.11(SOURCE)
VRECT: BR1.1(+DC) BR2.1(+DC) C34.1 D8.2 R48.1 T2.3
N4285024: C1.2 R1.1 U1.13(BPH)
N4285032: C4.1 C5.1 R1.2 R3.1
N4285050: C1.1 C2.2 C4.2 C5.2 T1.1 U1.15(HB)
N4286456: C2.1 U1.14(5VH)
N4298336: D5.2 T1.6
N4344251: Q3.3(COLLECTOR) R9.1 R72.2 U1.5(PP)
N4347891: C7.1 R6.1 U1.8(BP)
N4369660: R36.1 U4.3(IS)
N4383576: R29.2 U4.9(G1)
N4403571: R21.2 U4.8(G2)
N4411199: R37.1 R38.1
N4411203: C28.1 R38.2
N4415619: C26.1 R34.2
N4433947: Q11.1(G) R28.2 R29.1
N4443813: FL5.1 Q5.2(D) Q6.3(D)
N4539125: Q5.1(G) R19.2 R21.1
N4545785: D3.1 R3.2
N11972126: C13.1 D5.1 R58.2 R82.2 VR2.1
N12003586: Q3.1(BASE) R7.2
N12025663: R25.2 U4.10(D2)
N12156031: D6.2 T1.7
N12157735: Q9.2(S) R31.2 R32.1
N12157737: R32.2 U4.11(D1)
N12157825: Q6.2(S) R23.2 R25.1
N12357991: R36.2 R37.2
N12371547: C32.1 F1.1 J1.1
N12371579: C35.1 L1.1 L4.4 R83.1 R85.2 RV1.1
N12371619: BR1.2(AC1) BR2.2(AC1) C33.1 C36.1 L1.2 R42.1 R83.2
N12371639: BR1.3(AC2) BR2.3(AC2) L2.2
N12371737: C38.2 J3.1 RL1.3(COMMON) RT1.1
N12371917: C35.2 L1.3 L4.3 R84.1 R86.2 RV1.2
N12371921: C36.2 C37.2 L1.4 L2.1 R43.2 R84.2
N12372235: D7.2 Q10.3(D) RL1.2(COIL2)
N12372625: T2.4 U6.13(D)
N12372637: R47.2 R49.1
N12372641: C48.1 R55.2 R57.1 U6.7(FB)
N12372649: C43.1 R53.1 U6.9(PGT)
N12372683: C42.1 R54.1 U6.6(C)
N12372755: R48.2 R50.1
N12372759: R50.2 R51.1
N12372767: C45.1 R51.2 R56.1 U6.5(V)
N12372775: R49.2 R55.1
N12372865: C47.1 Q2.2(EMITTER) U6.1(Vcc)
N12372869: C42.2 C43.2 C44.2 C45.2 C46.2 C47.2 C48.2 R53.2 R56.2 R57.2 U6.4(G) VR3.2
N12372873: C44.1 U6.3(REF)
N12373065: C46.1 R54.2
N12432169: FL4.1 Q9.3(D) Q11.2(D)
N12432631: Q6.1(G) R20.2 R23.1
N12432635: Q9.1(G) R27.2 R31.1
N12449925: D4.2 R58.1
N12454383: Q2.3(COLLECTOR) R52.2 R71.1
N12461790: D7.1 R44.2
N12462026: Q10.1(G) R45.1 R46.1
N12462864: D2.2 U1.9(BM)
N12465647: C8.1 C58.2 T1.3
N12471388: Q4.3(COLLECTOR) R10.1 R12.2
N12471928: C10.1 D6.1 R10.2
N12472447: Q7.1(BASE) R24.2 VR6.1
N12472558: Q7.3(COLLECTOR) R22.1 R24.1
N12474001: D1.2 T1.4
N12474629: C3.1 D1.1 Q1.3(COLLECTOR) R2.1
N12474978: Q1.1(BASE) R2.2 VR1.1
N12551412: R42.2 U5.1(NC1) U5.2(D1) U5.3(NC2) U5.4(NC3)
N12551460: R43.1 U5.5(NC4) U5.6(NC5) U5.7(D2) U5.8(NC8)
N12570914: R63.2 R64.1
N12570918: R63.1 R65.2
N12570922: R64.2 R73.1 U1.2(L)
N12631063: Q2.1(BASE) R71.2 VR3.1
N12672110: C54.1 T1.12
N12720122: Q1.2(EMITTER) R81.2
N12721764: D11.1 R52.1
N12722777: C60.1 F1.2 L4.1 R85.1
N12722869: C60.2 L4.2 R86.1 RL1.4(NO) RT1.2
N12733627: C70.1 GND1.1 L5.4 R87.2
N12734004: +60V1.1 C70.2 L5.3 R88.2
N12796192: R40.1 U4.6(PS)
N12838446: Q4.1(BASE) R12.1 VR4.1

Not connected (* = marked no-connect by the designer): HS41 1 2; T1 2 9 10; T2 1 2 5 7 8 9 10 11 12; U4 13(NC13) 24(NC24)

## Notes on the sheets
sheet 1
- 2T
- 1T
- 720W LCS_SR PRIMARY
sheet 2
- 3T
- 3T
- GND
- PRIMARY
- 720W LCS_SR SECONDARY
sheet 3
- AC Input
  90-264 VAC
sheet 4
- For Mounting ESIP 16/13 to Heatsink
